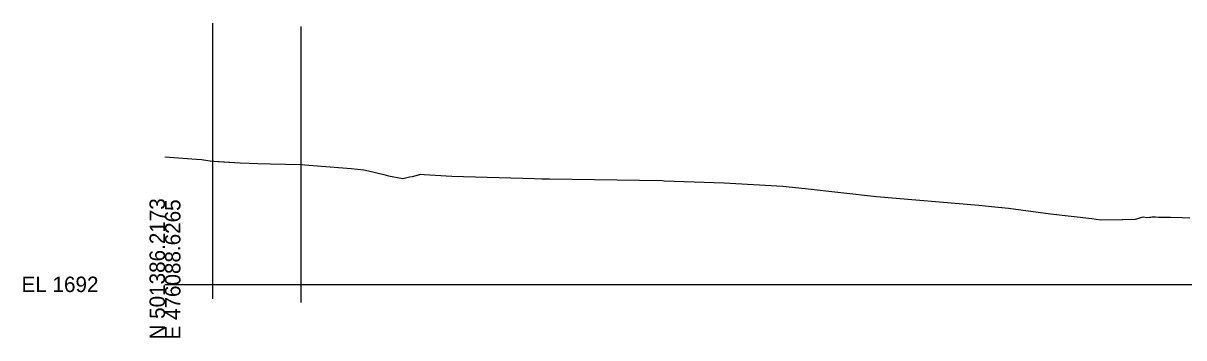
# Model space of a CAD drawing. Extents: x 78027 to 79855, y -93601 to -93005.
# Drawn here: x 78026.8 to 78237.1, y -93086.9 to -93029.9 of the extents above; entities that cross this region are included whole.
import ezdxf

# ---------------------------------------------------------------- set-up
doc = ezdxf.new("R2010")
doc.units = 0
for name, color, linetype in [('Exist Cross Section Cell', 7, 'Continuous'), ('Exist XS Ground Line', 7, 'Continuous'), ('Scratch_Level_0', 7, 'Continuous'), ('Scratch_Level_4', 7, 'Continuous'), ('Scratch_Level_5', 7, 'Continuous'), ('Scratch_Level_6', 7, 'Continuous')]:
    doc.layers.add(name, color=color, linetype=linetype)

msp = doc.modelspace()

# ---------------------------------------------------------------- linework, layer by layer
at = {"layer": 'Exist Cross Section Cell'}
msp.add_line((78052.48, -93077.22), (78252.48, -93077.22), dxfattribs=at)
at = {"layer": 'Exist XS Ground Line'}
for p, q in [((78052.48, -93054.09), (78058.22, -93054.55)), ((78058.22, -93054.55), (78059.09, -93054.58)), ((78059.09, -93054.58), (78061.01, -93054.87)), ((78061.01, -93054.87), (78061.31, -93054.88)), ((78061.31, -93054.88), (78066.09, -93055.16)), ((78066.09, -93055.16), (78069.31, -93055.31)), ((78069.31, -93055.31), (78071.62, -93055.36)), ((78071.62, -93055.36), (78077.05, -93055.5)), ((78077.05, -93055.5), (78086.23, -93056.19)), ((78086.23, -93056.19), (78088.53, -93056.46)), ((78088.53, -93056.46), (78089.36, -93056.64)), ((78089.36, -93056.64), (78092.14, -93057.33)), ((78092.14, -93057.33), (78092.95, -93057.53)), ((78092.95, -93057.53), (78095.6, -93058.01)), ((78095.6, -93058.01), (78096.81, -93057.74)), ((78096.81, -93057.74), (78097.34, -93057.69)), ((78097.34, -93057.69), (78098.65, -93057.3)), ((78098.65, -93057.3), (78098.82, -93057.24)), ((78098.82, -93057.24), (78099.45, -93057.28)), ((78099.45, -93057.28), (78104.43, -93057.59)), ((78104.43, -93057.59), (78119.43, -93058.05)), ((78119.43, -93058.05), (78120.75, -93058.07)), ((78120.75, -93058.07), (78122.14, -93058.12)), ((78122.14, -93058.12), (78142.56, -93058.42)), ((78142.56, -93058.42), (78142.95, -93058.43)), ((78142.95, -93058.43), (78153.78, -93058.81)), ((78153.78, -93058.81), (78164.46, -93059.42)), ((78164.46, -93059.42), (78168.45, -93059.86)), ((78168.45, -93059.86), (78181.4, -93061.28)), ((78181.4, -93061.28), (78199.95, -93062.84)), ((78199.95, -93062.84), (78202.25, -93063.09)), ((78202.25, -93063.09), (78205.3, -93063.43)), ((78205.3, -93063.43), (78212.93, -93064.44)), ((78212.93, -93064.44), (78220.42, -93065.3)), ((78220.42, -93065.3), (78221.97, -93065.52)), ((78221.97, -93065.52), (78225.94, -93065.49)), ((78225.94, -93065.49), (78225.99, -93065.49)), ((78225.99, -93065.49), (78228.33, -93065.4)), ((78228.33, -93065.4), (78229.72, -93065)), ((78229.72, -93065), (78230.37, -93065.1)), ((78230.37, -93065.1), (78231.36, -93064.99)), ((78231.36, -93064.99), (78231.47, -93064.99)), ((78231.47, -93064.99), (78231.57, -93064.99)), ((78231.57, -93064.99), (78231.68, -93065)), ((78231.68, -93065), (78231.96, -93065)), ((78231.96, -93065), (78232.51, -93065.04)), ((78232.51, -93065.04), (78233.1, -93065.07)), ((78233.1, -93065.07), (78234.68, -93065.06)), ((78234.68, -93065.06), (78236.82, -93065.11)), ((78236.82, -93065.11), (78238.15, -93065.18))]:
    msp.add_line(p, q, dxfattribs=at)
at = {"layer": 'Scratch_Level_0'}
msp.add_lwpolyline([(78052.48, -93054.09), (78058.22, -93054.55), (78059.09, -93054.58), (78061.01, -93054.87), (78066.09, -93055.16), (78069.31, -93055.31), (78071.62, -93055.36), (78077.05, -93055.5), (78086.23, -93056.19), (78088.53, -93056.46), (78089.36, -93056.64), (78092.14, -93057.33), (78092.95, -93057.53), (78095.6, -93058.01), (78096.81, -93057.74), (78097.34, -93057.69), (78098.82, -93057.24), (78099.45, -93057.28), (78104.43, -93057.59), (78119.43, -93058.05), (78120.75, -93058.07), (78122.14, -93058.12), (78142.56, -93058.42), (78142.95, -93058.43), (78153.78, -93058.81), (78164.46, -93059.42), (78168.45, -93059.86), (78181.4, -93061.28), (78199.95, -93062.84), (78202.25, -93063.09), (78205.3, -93063.43), (78212.93, -93064.44), (78220.42, -93065.3), (78221.97, -93065.52), (78225.99, -93065.49), (78228.33, -93065.4), (78229.72, -93065), (78230.37, -93065.1), (78231.96, -93065), (78232.51, -93065.04), (78233.1, -93065.07), (78234.68, -93065.06), (78236.82, -93065.11), (78238.15, -93065.18)], dxfattribs=at)
at = {"layer": 'Scratch_Level_4'}
for p, q in [((78061.08, -93029.87), (78061.08, -93079.87)), ((78077.09, -93030.5), (78077.09, -93080.5))]:
    msp.add_line(p, q, dxfattribs=at)
at = {"layer": 'Scratch_Level_5'}
msp.add_lwpolyline([(78052.48, -93054.09), (78058.22, -93054.55), (78059.09, -93054.58), (78061.01, -93054.87), (78066.09, -93055.16), (78069.31, -93055.31), (78071.62, -93055.36), (78077.05, -93055.5), (78086.23, -93056.19), (78088.53, -93056.46), (78089.36, -93056.64), (78092.14, -93057.33), (78092.95, -93057.53), (78095.6, -93058.01), (78096.81, -93057.74), (78097.34, -93057.69), (78098.82, -93057.24), (78099.45, -93057.28), (78104.43, -93057.59), (78119.43, -93058.05), (78120.75, -93058.07), (78122.14, -93058.12), (78142.56, -93058.42), (78142.95, -93058.43), (78153.78, -93058.81), (78164.46, -93059.42), (78168.45, -93059.86), (78181.4, -93061.28), (78199.95, -93062.84), (78202.25, -93063.09), (78205.3, -93063.43), (78212.93, -93064.44), (78220.42, -93065.3), (78221.97, -93065.52), (78225.99, -93065.49), (78228.33, -93065.4), (78229.72, -93065), (78230.37, -93065.1), (78231.96, -93065), (78232.51, -93065.04), (78233.1, -93065.07), (78234.68, -93065.06), (78236.82, -93065.11), (78238.15, -93065.18)], dxfattribs=at)
at = {"layer": 'Scratch_Level_6'}
msp.add_lwpolyline([(78052.48, -93054.09), (78058.22, -93054.55), (78059.09, -93054.58), (78061.01, -93054.87), (78066.09, -93055.16), (78069.31, -93055.31), (78071.62, -93055.36), (78077.05, -93055.5), (78086.23, -93056.19), (78088.53, -93056.46), (78089.36, -93056.64), (78092.14, -93057.33), (78092.95, -93057.53), (78095.6, -93058.01), (78096.81, -93057.74), (78097.34, -93057.69), (78098.82, -93057.24), (78099.45, -93057.28), (78104.43, -93057.59), (78119.43, -93058.05), (78120.75, -93058.07), (78122.14, -93058.12), (78142.56, -93058.42), (78142.95, -93058.43), (78153.78, -93058.81), (78164.46, -93059.42), (78168.45, -93059.86), (78181.4, -93061.28), (78199.95, -93062.84), (78202.25, -93063.09), (78205.3, -93063.43), (78212.93, -93064.44), (78220.42, -93065.3), (78221.97, -93065.52), (78225.99, -93065.49), (78228.33, -93065.4), (78229.72, -93065), (78230.37, -93065.1), (78231.96, -93065), (78232.51, -93065.04), (78233.1, -93065.07), (78234.68, -93065.06), (78236.82, -93065.11), (78238.15, -93065.18)], dxfattribs=at)

# ---------------------------------------------------------------- texts
at = {"layer": 'Exist Cross Section Cell'}
for s, p in [('N 501386.2173', (78052.48, -93087.22)), ('E 476088.6265', (78055.28, -93087.22))]:
    msp.add_text(s, height=2.8, rotation=90, dxfattribs=at).set_placement(p)
msp.add_text('EL 1692', height=2.8, dxfattribs=at).set_placement((78026.48, -93078.62))

doc.saveas('drawing.dxf')
